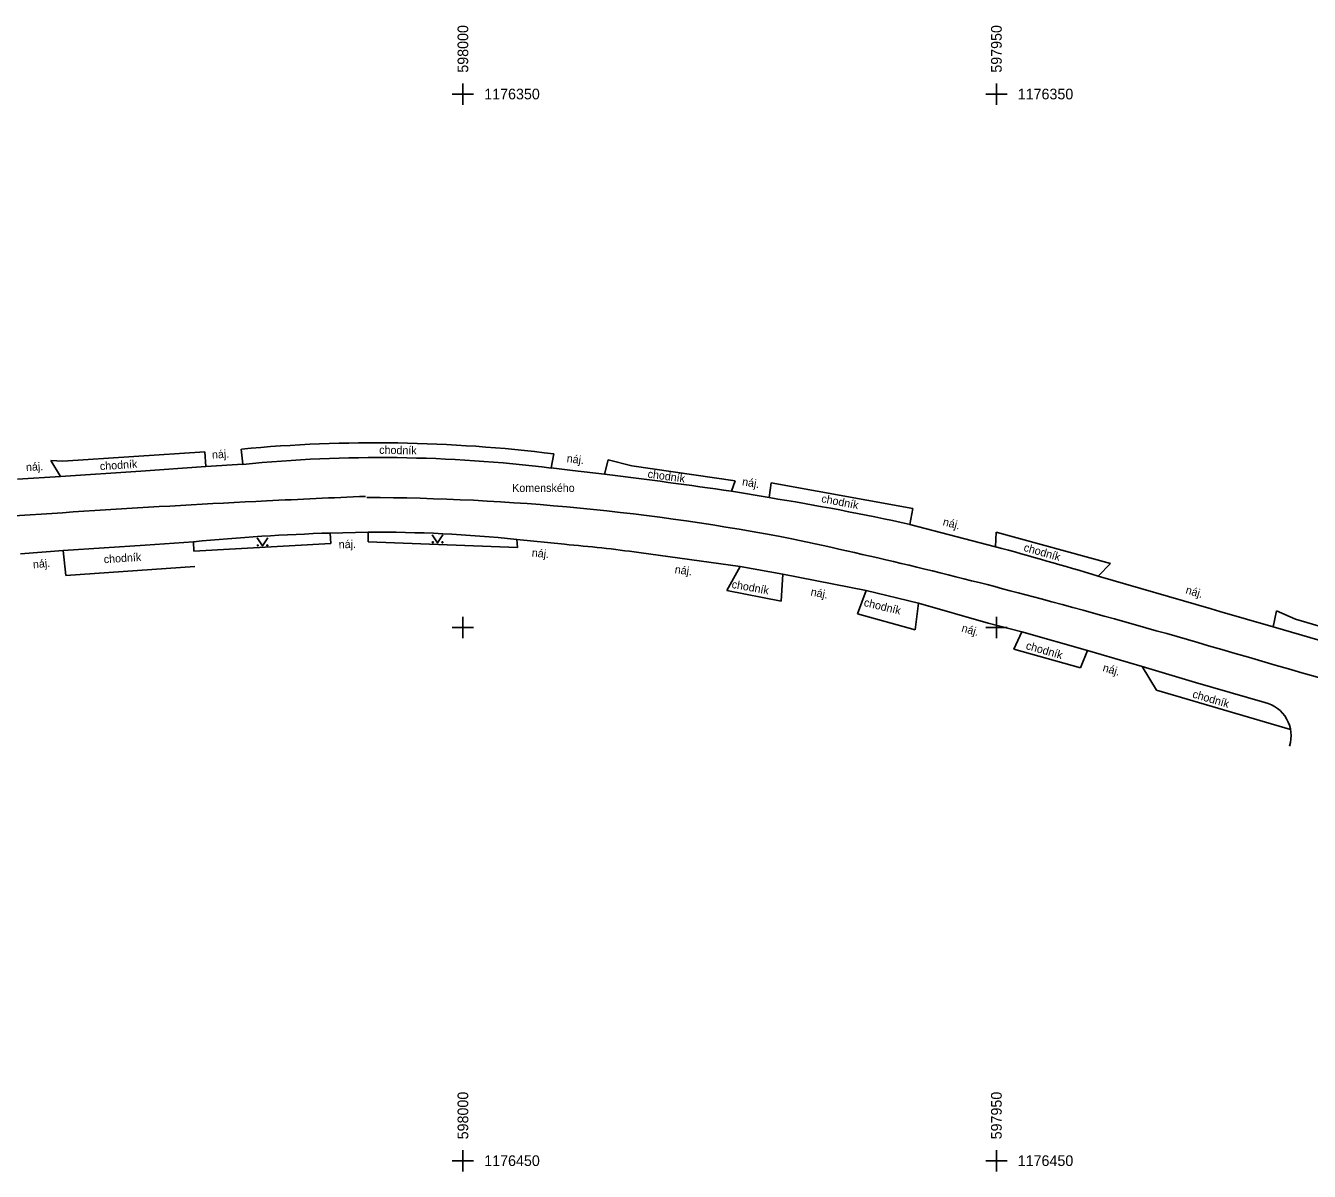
# Model space of a CAD drawing. Extents: x -598160 to -596067, y -1177005 to -1176344.
# Drawn here: x -598041 to -597920.7, y -1176451 to -1176343.6 of the extents above; entities that cross this region are included whole.
import ezdxf

# ---------------------------------------------------------------- set-up
doc = ezdxf.new("R2010")
doc.units = 0
for name, color, linetype in [('hektametrová síť', 7, 'Continuous'), ('obruba +0 cm', 7, 'Continuous'), ('obruba +12 cm', 7, 'Continuous'), ('obruba +3 cm', 7, 'Continuous'), ('popis ploch', 7, 'Continuous'), ('rozhraní ploch', 7, 'Continuous'), ('vodorovné značení', 7, 'Continuous'), ('zeleň', 7, 'Continuous')]:
    doc.layers.add(name, color=color, linetype=linetype)

msp = doc.modelspace()

# ---------------------------------------------------------------- linework, layer by layer
at = {"layer": 'hektametrová síť'}
for p, q in [((-598000, -1176351), (-598000, -1176349)), ((-597950, -1176351), (-597950, -1176349)), ((-598001, -1176350), (-597999, -1176350)), ((-597951, -1176350), (-597949, -1176350)), ((-598000, -1176401), (-598000, -1176399)), ((-597950, -1176401), (-597950, -1176399)), ((-598001, -1176400), (-597999, -1176400)), ((-597951, -1176400), (-597949, -1176400)), ((-598000, -1176451), (-598000, -1176449)), ((-597950, -1176451), (-597950, -1176449)), ((-598001, -1176450), (-597999, -1176450)), ((-597951, -1176450), (-597949, -1176450))]:
    msp.add_line(p, q, dxfattribs=at)
at = {"layer": 'obruba +0 cm'}
for p, q in [((-598020.63, -1176384.71), (-598024.1, -1176384.93)), ((-597989.72, -1176385.28), (-597991.72, -1176385.06)), ((-597986.73, -1176385.64), (-597989.72, -1176385.28)), ((-598037.7, -1176385.85), (-598041.75, -1176386.11)), ((-597971.31, -1176387.83), (-597974.83, -1176387.23)), ((-598012.43, -1176391.16), (-598008.87, -1176391.08)), ((-597994.95, -1176391.75), (-597990.47, -1176392.21)), ((-597983.51, -1176392.98), (-597974, -1176394.3)), ((-597970.01, -1176395.01), (-597962.21, -1176396.56)), ((-597957.29, -1176397.74), (-597950.76, -1176399.6)), ((-597929.06, -1176398.52), (-597929.86, -1176398.25)), ((-597924.07, -1176399.95), (-597929.06, -1176398.52)), ((-597950.76, -1176399.6), (-597947.61, -1176400.42))]:
    msp.add_line(p, q, dxfattribs=at)
at = {"layer": 'obruba +12 cm'}
for p, q in [((-598030.19, -1176385.35), (-598037.7, -1176385.85)), ((-598024.1, -1176384.93), (-598030.19, -1176385.35)), ((-598037.45, -1176392.78), (-598029.77, -1176392.3)), ((-598029.77, -1176392.3), (-598025.25, -1176391.98)), ((-597974, -1176394.3), (-597970.01, -1176395.01)), ((-597962.21, -1176396.56), (-597957.29, -1176397.74)), ((-597909.36, -1176404.24), (-597924.07, -1176399.95)), ((-597947.61, -1176400.42), (-597941.45, -1176402.18)), ((-597936.35, -1176403.68), (-597931.33, -1176405.16)), ((-597931.33, -1176405.16), (-597924.85, -1176407.04))]:
    msp.add_line(p, q, dxfattribs=at)
for centre, radius, start, end in [((-598007.74, -1176514.5), 130.42, 82.9427, 95.6701), ((-598057.26, -1176958.82), 577.5, 81.79401, 82.98516), ((-598007.91, -1176615.6), 230.69, 77.5295, 80.87), ((-598006.2, -1176589.21), 198.15, 91.8022, 95.5174), ((-598007.86, -1176515.11), 124.03, 84.0239, 90.4648), ((-598001.58, -1176524.47), 132.72, 82.1753, 85.1985), ((-598050.69, -1176762.57), 383.56, 73.2994, 74.794), ((-597925.57, -1176410.15), 3.19, 342.1688, 76.9583)]:
    msp.add_arc(centre, radius, start, end, dxfattribs=at)
at = {"layer": 'obruba +3 cm'}
for p, q in [((-597958.1, -1176390.35), (-597950.09, -1176392.44)), ((-598041.46, -1176393.12), (-598037.45, -1176392.78)), ((-597940.47, -1176395.19), (-597929.86, -1176398.25)), ((-597941.45, -1176402.18), (-597936.35, -1176403.68))]:
    msp.add_line(p, q, dxfattribs=at)
at = {"layer": 'rozhraní ploch'}
for p, q in [((-598037.49, -1176384.42), (-598024.18, -1176383.55)), ((-598024.18, -1176383.55), (-598024.1, -1176384.93)), ((-598020.63, -1176384.71), (-598020.77, -1176383.28)), ((-597991.48, -1176383.73), (-597991.72, -1176385.06)), ((-597986.73, -1176385.64), (-597986.38, -1176384.29)), ((-597986.38, -1176384.29), (-597984.18, -1176384.87)), ((-598038.61, -1176384.37), (-598037.49, -1176384.42)), ((-598038.61, -1176384.37), (-598037.7, -1176385.85)), ((-597984.18, -1176384.87), (-597974.47, -1176386.27)), ((-597974.47, -1176386.27), (-597974.83, -1176387.23)), ((-597971.31, -1176387.83), (-597971.11, -1176386.46)), ((-597971.11, -1176386.46), (-597957.83, -1176388.86)), ((-597957.83, -1176388.86), (-597958.1, -1176390.35)), ((-598012.43, -1176391.16), (-598012.38, -1176392.13)), ((-598008.88, -1176391.97), (-598008.87, -1176391.08)), ((-597950.09, -1176392.44), (-597950.03, -1176391.07)), ((-597950.03, -1176391.07), (-597939.31, -1176394.02)), ((-598025.21, -1176392.85), (-598025.25, -1176391.98)), ((-598012.38, -1176392.13), (-598025.21, -1176392.85)), ((-597994.89, -1176392.52), (-598008.88, -1176391.97)), ((-597994.95, -1176391.75), (-597994.89, -1176392.52)), ((-598037.45, -1176392.78), (-598037.23, -1176395.15)), ((-598025.13, -1176394.3), (-598037.23, -1176395.15)), ((-597975.25, -1176396.55), (-597974, -1176394.3)), ((-597970.01, -1176395.01), (-597970.18, -1176397.54)), ((-597939.31, -1176394.02), (-597940.47, -1176395.19)), ((-597970.18, -1176397.54), (-597975.25, -1176396.55)), ((-597963.03, -1176398.74), (-597962.21, -1176396.56)), ((-597957.61, -1176400.22), (-597963.03, -1176398.74)), ((-597957.29, -1176397.74), (-597957.61, -1176400.22)), ((-597924.07, -1176399.95), (-597923.76, -1176398.44)), ((-597923.76, -1176398.44), (-597921.97, -1176399.22)), ((-597921.97, -1176399.22), (-597908.81, -1176403.11)), ((-597948.35, -1176402.05), (-597947.61, -1176400.42)), ((-597942.13, -1176403.81), (-597948.35, -1176402.05)), ((-597941.45, -1176402.18), (-597942.13, -1176403.81)), ((-597934.98, -1176405.9), (-597936.35, -1176403.68)), ((-597922.43, -1176409.57), (-597934.98, -1176405.9))]:
    msp.add_line(p, q, dxfattribs=at)
msp.add_arc((-598008.19, -1176518.2), 135.5, 82.9146, 95.325, dxfattribs=at)
at = {"layer": 'vodorovné značení'}
for centre, radius, start, end in [((-597959.43, -1177575.57), 1188.89, 92.39575, 92.8434), ((-598009.51, -1176599.88), 212.05, 79.036, 89.8648), ((-597966.25, -1177450.55), 1063.69, 92.8106, 94.54816), ((-598061.31, -1176825.25), 443.23, 74.8924, 78.003), ((-598136.21, -1177108.01), 735.74, 73.73419, 75.00055), ((-599574.27, -1182105.77), 5936.27, 73.519077, 73.920875)]:
    msp.add_arc(centre, radius, start, end, dxfattribs=at)
at = {"layer": 'zeleň'}
for points in [[(-598002.87, -1176391.33), (-598002.37, -1176392.08), (-598001.87, -1176391.33)], [(-598019.27, -1176391.62), (-598018.77, -1176392.37), (-598018.27, -1176391.62)]]:
    msp.add_lwpolyline(points, dxfattribs=at)
for centre in [(-598019.23, -1176392.32), (-598018.33, -1176392.32), (-598002.82, -1176392.03), (-598001.92, -1176392.03)]:
    msp.add_circle(centre, 0.05, dxfattribs=at)

# ---------------------------------------------------------------- texts
at = {"layer": 'hektametrová síť'}
for s, p in [('598000', (-597999.5, -1176348)), ('597950', (-597949.5, -1176348)), ('598000', (-597999.5, -1176448)), ('597950', (-597949.5, -1176448))]:
    msp.add_text(s, height=1, rotation=90, dxfattribs=at).set_placement(p)
for s, p in [('1176350', (-597998, -1176350.5)), ('1176350', (-597948, -1176350.5)), ('1176450', (-597998, -1176450.5)), ('1176450', (-597948, -1176450.5))]:
    msp.add_text(s, height=1, dxfattribs=at).set_placement(p)
at = {"layer": 'popis ploch'}
for s, rotation, p in [('chodník', 359.058, (-598007.85, -1176383.73)), ('chodník', 3.809, (-598034, -1176385.27)), ('náj.', 3.6277, (-598023.5, -1176384.19)), ('náj.', 353.1346, (-597990.3, -1176384.51)), ('náj.', 3.6732, (-598040.93, -1176385.36)), ('chodník', 352.3445, (-597982.72, -1176385.96)), ('náj.', 350.3266, (-597973.87, -1176386.68)), ('chodník', 349.0714, (-597966.45, -1176388.26)), ('náj.', 345.3762, (-597955.07, -1176390.42)), ('náj.', 1.2873, (-598011.63, -1176392.59)), ('náj.', 354.1375, (-597993.57, -1176393.35)), ('chodník', 344.0698, (-597947.5, -1176392.82)), ('náj.', 4.8464, (-598040.27, -1176394.47)), ('chodník', 3.5763, (-598033.64, -1176393.99)), ('náj.', 352.0978, (-597980.18, -1176394.91)), ('chodník', 349.9101, (-597974.85, -1176396.3)), ('náj.', 343.9121, (-597932.32, -1176396.81)), ('náj.', 348.7607, (-597967.45, -1176397)), ('chodník', 346.5131, (-597962.47, -1176397.99)), ('náj.', 344.101, (-597953.32, -1176400.38)), ('chodník', 344.0546, (-597947.29, -1176402.02)), ('náj.', 343.6105, (-597940.09, -1176404.09)), ('chodník', 343.8213, (-597931.68, -1176406.57))]:
    msp.add_text(s, height=0.75, rotation=rotation, dxfattribs=at).set_placement(p)
msp.add_text('Komenského', height=0.75, dxfattribs=at).set_placement((-597995.38, -1176387.3))

doc.saveas('drawing.dxf')
